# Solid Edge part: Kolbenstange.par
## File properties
Author: bmolnar
Last saved by: bmolnar
Revision: 78
Sűrűség: 0,000 kg/m^3
Pontosság: 0,990
Username: bmolnar
Dokumentum tartalom típus: 0
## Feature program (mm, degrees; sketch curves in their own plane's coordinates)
base feature "unnamed BaseFeature 1"
sketch for "unnamed Protrusion 1" plane through (0, 0, 0) normal (-1, 0, 0) x-axis (0, -1, 0)
  circle centre (0, 0) radius 40
extrude "unnamed Protrusion 1" add finite 19.15 along +normal
sketch for "Kihúzás_2" #1 plane through (0, 0, 0) normal (-1, 0, 0) x-axis (0, -1, 0)
  circle centre (0, 0) radius 10
sketch for "Kihúzás_2" #2 plane through (0, 0, 0) normal (-1, 0, 0) x-axis (0, -1, 0)
  circle centre (0, 0) radius 40
extrude "Kihúzás_2" add finite 11.15 along -normal
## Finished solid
Body 1: solid body, 16 faces, 22 edges, 8 vertices.
  Faces by surface: plane 7, cylinder 4, cone 3, torus 2
  Edges by curve: circle 12, line 6, curve on surface 2, ellipse 2
Bounding box of the edges (mm; curved faces can reach further): 71.150 x 80.000 x 80.000, from (-19.15, -40, -40) to (52, 40, 40).
Cylindrical faces by radius (mm): R4.188 x1, R5.125 x1, R10 x1, R40 x1
Conical faces (half-angle, radius in mm at the cone's reference point): 45 deg R4.588 x1, 45 deg R5.225 x1, 59 deg R2.094 x1
Toroidal faces (ring radius, tube radius in mm): R4.925 r0.2 x1, R8.2 r1.8 x1
Planar faces by outward normal: +x 2, +z 1, -x 1, -z 1, oblique 2
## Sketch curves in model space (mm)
circle centre (0, 0, 0) radius 10
circle centre (0, 0, 0) radius 40
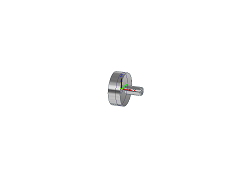
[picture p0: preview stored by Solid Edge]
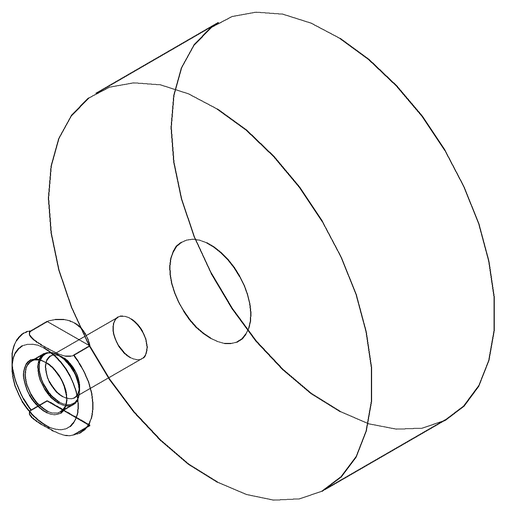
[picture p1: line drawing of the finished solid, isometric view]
